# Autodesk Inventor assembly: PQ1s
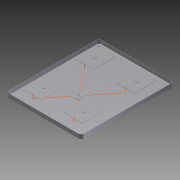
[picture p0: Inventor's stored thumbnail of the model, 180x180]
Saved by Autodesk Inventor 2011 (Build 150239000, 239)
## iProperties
Created: 2015-03
Part Number: PQ1s
Document SubType Name: Assembly
Designer: Evgeny
Mass: 166.215 g
Surface Area: 2771.24 cm^2
Volume: 166.215 cm^3
Density: 1 g/cm^3
Author: Evgeny
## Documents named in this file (6)
- D:\Autodesk Invertor 2011\Projects2014\Antenna\PanelJomy\PQ1s.iam
- D:\Autodesk Invertor 2011\Projects2014\Antenna\PanelJomy\PQ1s.ipt
- D:\Autodesk Invertor 2011\Projects2014\Antenna\PanelJomy\PZq.ipt
- D:\Autodesk Invertor 2011\Projects2014\Antenna\PanelJomy\PQbolt4.ipt
- D:\Autodesk Invertor 2011\Projects2014\Antenna\PanelJomy\PJcup240x195.ipt
- D:\Autodesk Invertor 2011\Projects2014\Antenna\PanelJomy\PQ1iso.ipt
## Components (11 placed, 5 different names)
1. PQ1s:1 — Совмещение:3, Совмещение:4, Совмещение:5, Совмещение:6, Совмещение:7, Совмещение:8, Вставка:1, Вставка:2, Вставка:3, Вставка:4, Совмещение:9, Совмещение:12, Совмещение:13
2. PZq:1 — Совмещение:1, Совмещение:3, Совмещение:7
3. PZq:2 — Совмещение:2, Совмещение:4, Совмещение:8
4. PZq:3 — Совмещение:1, Совмещение:5
5. PZq:4 — Совмещение:2, Совмещение:6
6. PQbolt4:1 — Вставка:1, Совмещение:11
7. PQbolt4:2 — Вставка:2
8. PQbolt4:3 — Вставка:3, Совмещение:10
9. PQbolt4:4 — Вставка:4
10. PJcup240x195:1 — Совмещение:9, Совмещение:10, Совмещение:11
11. PQ1iso:1 — Совмещение:12, Совмещение:13
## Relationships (17: Mate 13, Insert 4)
- Совмещение:1 [Mate]: PZq:1 ↔ PZq:3
- Совмещение:2 [Mate]: PZq:2 ↔ PZq:4
- Совмещение:3 [Mate]: PQ1s:1 ↔ PZq:1
- Совмещение:4 [Mate]: PQ1s:1 ↔ PZq:2
- Совмещение:5 [Mate]: PQ1s:1 ↔ PZq:3
- Совмещение:6 [Mate]: PQ1s:1 ↔ PZq:4
- Совмещение:7 [Mate]: PQ1s:1 ↔ PZq:1
- Совмещение:8 [Mate]: PQ1s:1 ↔ PZq:2
- Вставка:1 [Insert]: PQ1s:1 ↔ PQbolt4:1
- Вставка:2 [Insert]: PQ1s:1 ↔ PQbolt4:2
- Вставка:3 [Insert]: PQ1s:1 ↔ PQbolt4:3
- Вставка:4 [Insert]: PQ1s:1 ↔ PQbolt4:4
- Совмещение:9 [Mate]: PQ1s:1 ↔ PJcup240x195:1
- Совмещение:10 [Mate]: PQbolt4:3 ↔ PJcup240x195:1
- Совмещение:11 [Mate]: PQbolt4:1 ↔ PJcup240x195:1
- Совмещение:12 [Mate]: PQ1s:1 ↔ PQ1iso:1
- Совмещение:13 [Mate]: PQ1s:1 ↔ PQ1iso:1
